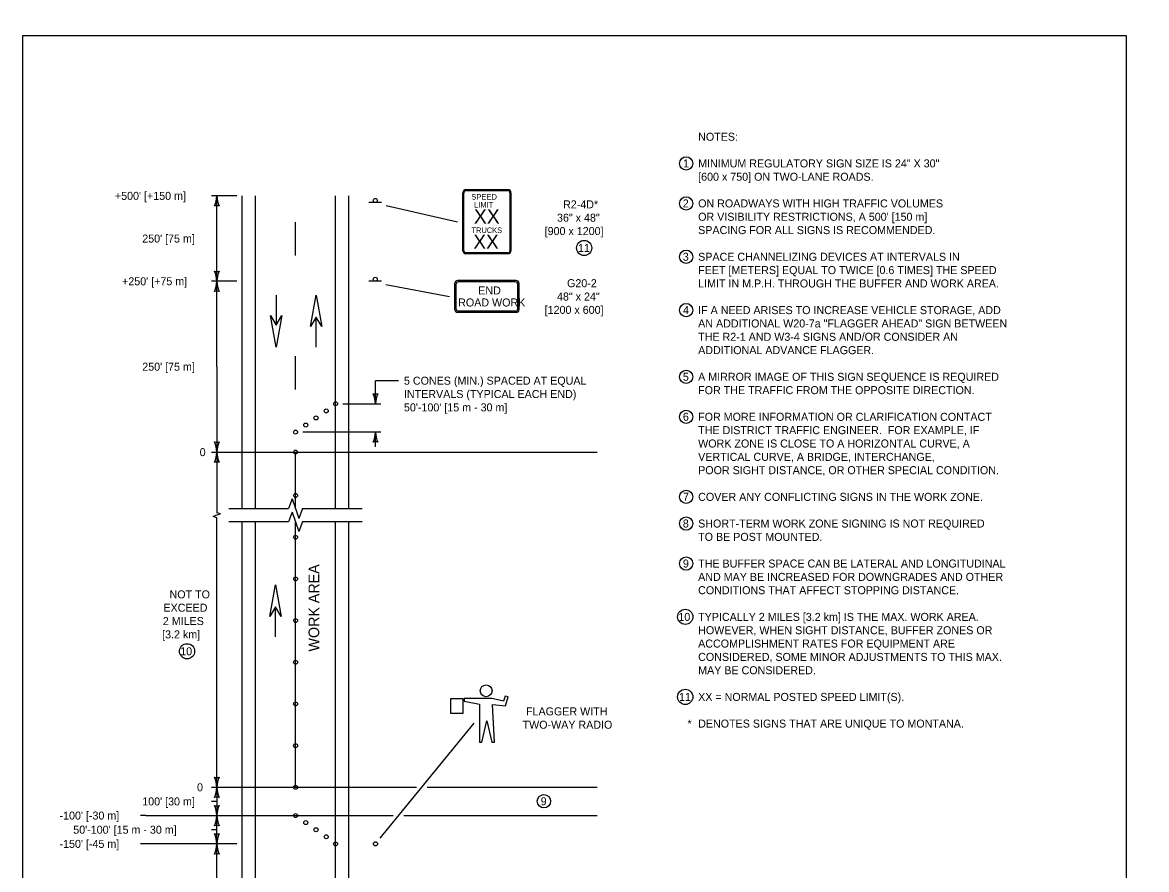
# Model space of a CAD drawing. Extents: x 49987.3 to 50021, y 49987.6 to 50011.4.
# Drawn here: x 50000.34 to 50008.76, y 50005.01 to 50011.36 of the extents above; entities that cross this region are included whole.
import ezdxf

# ---------------------------------------------------------------- set-up
doc = ezdxf.new("R2010")
doc.units = 0
for name, color, linetype in [('Default', 7, 'Continuous'), ('Level 1', 7, 'Continuous'), ('Level 2', 7, 'Continuous'), ('Level 3', 7, 'Continuous'), ('Level 6', 7, 'Continuous')]:
    doc.layers.add(name, color=color, linetype=linetype)

msp = doc.modelspace()

# ---------------------------------------------------------------- linework, layer by layer
at = {"layer": 'Default'}
for p, q in [((50001.7932, 50005.5227), (50001.7532, 50005.5226)), ((50001.2613, 50005.4166), (50001.2213, 50005.4166)), ((50001.7932, 50005.3106), (50001.7532, 50005.3106)), ((50001.2613, 50005.2045), (50001.2213, 50005.2045))]:
    msp.add_line(p, q, dxfattribs=at)
at = {"layer": 'Level 1'}
for p, q in [((50008.7646, 50011.3628), (50008.7646, 50011.3628)), ((50003.9761, 50010.1089), (50003.6611, 50010.1089)), ((50003.9761, 50010.1013), (50003.6611, 50010.1013)), ((50001.9831, 50007.7182), (50001.9831, 50010.0631)), ((50002.0831, 50007.7182), (50002.0831, 50010.0631)), ((50002.6831, 50007.7182), (50002.6831, 50010.0631)), ((50002.783, 50007.7182), (50002.783, 50010.0631)), ((50003.6386, 50009.6515), (50003.6386, 50010.0864)), ((50003.6462, 50009.6515), (50003.6462, 50010.0864)), ((50003.991, 50010.0864), (50003.991, 50009.6515)), ((50003.9986, 50010.0864), (50003.9986, 50009.6515)), ((50003.029, 50010.0128), (50002.9332, 50010.0128)), ((50002.3831, 50009.616), (50002.3831, 50009.8659)), ((50003.8221, 50009.9112), (50003.8221, 50009.9112)), ((50003.9761, 50009.6366), (50003.6611, 50009.6366)), ((50003.9761, 50009.629), (50003.6611, 50009.629)), ((50004.0386, 50009.4281), (50003.5986, 50009.4281)), ((50003.029, 50009.4225), (50002.9332, 50009.4225)), ((50003.5786, 50009.2081), (50003.5786, 50009.4081)), ((50003.5886, 50009.2131), (50003.5886, 50009.4031)), ((50004.0336, 50009.4181), (50003.6036, 50009.4181)), ((50004.0486, 50009.4031), (50004.0486, 50009.2131)), ((50004.0586, 50009.4081), (50004.0586, 50009.2081)), ((50002.2381, 50009.319), (50002.2381, 50009.0929)), ((50002.2384, 50009.319), (50002.2384, 50009.0929)), ((50004.0385, 50009.1881), (50003.5985, 50009.1881)), ((50004.0336, 50009.1981), (50003.6036, 50009.1981)), ((50002.5378, 50008.9287), (50002.5378, 50009.1545)), ((50002.5381, 50008.9287), (50002.5381, 50009.1545)), ((50002.3831, 50008.6118), (50002.3831, 50008.8617)), ((50002.3831, 50007.7167), (50002.3831, 50008.1415)), ((50001.9831, 50001.0011), (50001.9831, 50007.6183)), ((50002.083, 50001.0011), (50002.0831, 50007.6183)), ((50002.3831, 50005.6287), (50002.3831, 50007.6168)), ((50002.683, 50001.0011), (50002.6831, 50007.6183)), ((50002.783, 50001.0011), (50002.783, 50007.6183)), ((50002.2328, 50006.7559), (50002.2328, 50006.982)), ((50002.2331, 50006.7559), (50002.2331, 50006.982)), ((50003.9554, 50006.3127), (50003.9427, 50006.2732)), ((50003.9773, 50006.3072), (50003.9554, 50006.3127)), ((50003.9574, 50006.2383), (50003.9773, 50006.3072)), ((50003.5469, 50006.1813), (50003.5469, 50006.2938)), ((50003.5469, 50006.2938), (50003.6387, 50006.2938)), ((50003.6387, 50006.2938), (50003.6387, 50006.1813)), ((50003.8559, 50006.2932), (50003.6489, 50006.2932)), ((50003.6489, 50006.2932), (50003.6489, 50006.2746)), ((50003.6489, 50006.2746), (50003.7615, 50006.2524)), ((50003.7615, 50006.2524), (50003.7615, 50005.966)), ((50003.9427, 50006.2732), (50003.8559, 50006.2932)), ((50003.8745, 50005.966), (50003.8598, 50006.2494)), ((50003.8598, 50006.2494), (50003.9574, 50006.2383)), ((50003.6387, 50006.1813), (50003.5469, 50006.1813)), ((50003.7796, 50005.966), (50003.8179, 50006.1274)), ((50003.8179, 50006.1274), (50003.8562, 50005.966)), ((50003.7615, 50005.966), (50003.7796, 50005.966)), ((50003.8562, 50005.966), (50003.8745, 50005.966))]:
    msp.add_line(p, q, dxfattribs=at)
for points in [[(50008.6146, 50011.2628), (50000.3356, 50011.2628), (50000.3356, 50000.0624), (50008.6146, 50000.0624)], [(50002.4961, 50009.0823), (50002.5378, 50009.3186), (50002.5797, 50009.0823), (50002.5378, 50009.1545)], [(50002.2802, 50009.1654), (50002.2384, 50008.9287), (50002.1966, 50009.1654), (50002.2384, 50009.0931)], [(50002.1911, 50006.9095), (50002.2328, 50007.1462), (50002.2747, 50006.9095), (50002.2328, 50006.9817)]]:
    msp.add_lwpolyline(points, close=True, dxfattribs=at)
for points in [[(50003.9552, 50006.3126), (50003.9554, 50006.3127)], [(50003.9567, 50006.2386), (50003.9576, 50006.2395)], [(50003.6384, 50006.1813), (50003.6387, 50006.1817)]]:
    msp.add_lwpolyline(points, dxfattribs=at)
for centre, radius in [((50002.981, 50010.0283), 0.0152), ((50002.981, 50009.4379), 0.0152), ((50002.6831, 50008.5037), 0.015), ((50002.6135, 50008.4507), 0.015), ((50002.4599, 50008.3446), 0.015), ((50002.5367, 50008.3977), 0.015), ((50002.3831, 50008.2916), 0.015), ((50002.3831, 50008.1415), 0.015), ((50002.3831, 50007.8163), 0.015), ((50002.3831, 50007.5038), 0.015), ((50002.3831, 50007.1913), 0.015), ((50002.3831, 50006.8788), 0.015), ((50002.3831, 50006.5663), 0.015), ((50003.8123, 50006.352), 0.0442), ((50002.3831, 50006.2538), 0.015), ((50002.3831, 50005.9413), 0.015), ((50002.3831, 50005.6288), 0.015), ((50002.3831, 50005.4166), 0.015), ((50002.4599, 50005.3636), 0.015), ((50002.5367, 50005.3106), 0.015), ((50002.6135, 50005.2575), 0.015), ((50002.6831, 50005.2045), 0.015), ((50002.983, 50005.2045), 0.0152)]:
    msp.add_circle(centre, radius, dxfattribs=at)
for centre, radius, start, end in [((50003.6611, 50010.0864), 0.0225, 90, 180), ((50003.6611, 50010.0864), 0.0149, 90, 180), ((50003.9761, 50010.0864), 0.0225, 0, 90), ((50003.9761, 50010.0864), 0.0149, 0, 90), ((50003.6611, 50009.6515), 0.0225, 180, 270), ((50003.6611, 50009.6515), 0.0149, 180, 270), ((50003.9761, 50009.6515), 0.0225, 270, 0), ((50003.9761, 50009.6515), 0.0149, 270, 0), ((50003.5986, 50009.4081), 0.02, 90, 180), ((50004.0386, 50009.4081), 0.02, 360, 90), ((50003.6036, 50009.4031), 0.015, 90, 180), ((50004.0336, 50009.4031), 0.015, 360, 90), ((50003.5985, 50009.2081), 0.02, 180, 270), ((50003.6036, 50009.2131), 0.015, 180, 270), ((50004.0336, 50009.2131), 0.015, 270, 360), ((50004.0385, 50009.2081), 0.02, 270, 360)]:
    msp.add_arc(centre, radius, start, end, dxfattribs=at)
at = {"layer": 'Level 2'}
for centre, radius in [((50005.3124, 50010.3062), 0.05), ((50005.3124, 50010.0062), 0.05), ((50004.5478, 50009.6721), 0.0569), ((50005.3124, 50009.6062), 0.05), ((50005.3124, 50009.2062), 0.05), ((50005.3124, 50008.7062), 0.05), ((50005.3124, 50008.4062), 0.05), ((50005.3124, 50007.8062), 0.05), ((50005.3124, 50007.6062), 0.05), ((50005.3124, 50007.3062), 0.05), ((50005.3056, 50006.9062), 0.0569), ((50001.5698, 50006.6483), 0.0569), ((50005.3056, 50006.3062), 0.0569), ((50004.2461, 50005.5238), 0.05)]:
    msp.add_circle(centre, radius, dxfattribs=at)
at = {"layer": 'Level 3'}
for p, q in [((50001.9431, 50010.0631), (50001.7531, 50010.0631)), ((50001.7931, 50009.4225), (50001.7931, 50010.0631)), ((50003.0622, 50009.9905), (50003.5986, 50009.8689)), ((50001.9431, 50009.4225), (50001.7531, 50009.4225)), ((50001.9431, 50009.4225), (50001.7532, 50009.4225)), ((50001.7932, 50008.782), (50001.7932, 50009.4225)), ((50003.0602, 50009.3975), (50003.5386, 50009.3081)), ((50001.7932, 50008.782), (50001.7932, 50008.1415)), ((50002.983, 50008.5037), (50002.983, 50008.6771)), ((50003.1563, 50008.6771), (50002.983, 50008.6771)), ((50002.7381, 50008.5037), (50003.023, 50008.5037)), ((50003.023, 50008.2916), (50002.4381, 50008.2916)), ((50002.983, 50008.1815), (50002.983, 50008.2916)), ((50001.7532, 50008.1415), (50004.6462, 50008.1415)), ((50001.7932, 50008.1415), (50001.7932, 50007.6876)), ((50001.7932, 50007.6682), (50001.7658, 50007.6585)), ((50001.7932, 50007.6488), (50001.7658, 50007.6585)), ((50001.8206, 50007.6779), (50001.7932, 50007.6876)), ((50001.8206, 50007.6779), (50001.7932, 50007.6682)), ((50001.7932, 50005.6287), (50001.7932, 50007.6488)), ((50003.0179, 50005.2473), (50003.7215, 50006.1092)), ((50001.7531, 50005.6287), (50003.2893, 50005.6287)), ((50001.7932, 50005.6287), (50001.7932, 50005.4166)), ((50003.3693, 50005.6287), (50004.6461, 50005.6287)), ((50001.2613, 50005.4166), (50003.1162, 50005.4166)), ((50001.7932, 50005.2045), (50001.7932, 50005.4166)), ((50003.1962, 50005.4166), (50004.6461, 50005.4166)), ((50001.9431, 50005.2045), (50001.2613, 50005.2045)), ((50001.7932, 50001.3045), (50001.7932, 50005.2045))]:
    msp.add_line(p, q, dxfattribs=at)
for centre, radius, start, end in [((50001.571, 50010.0722), 0.2223, 337.45601, 357.63952), ((50002.0259, 50010.0745), 0.233, 182.82731, 202.07716), ((50001.7931, 50009.9348), 0.0548, 72.13882, 107.86118), ((50001.7931, 50009.5507), 0.0548, 252.13882, 287.86118), ((50001.5604, 50009.411), 0.233, 2.82731, 22.07716), ((50002.0153, 50009.4134), 0.2223, 157.45601, 177.63952), ((50001.571, 50009.4317), 0.2223, 337.45601, 357.63952), ((50001.7932, 50009.2943), 0.0548, 72.13882, 107.86118), ((50002.0259, 50009.434), 0.233, 182.82731, 202.07716), ((50002.983, 50008.6319), 0.0548, 252.13882, 287.86118), ((50002.7503, 50008.4922), 0.233, 2.82731, 22.07716), ((50003.2051, 50008.4945), 0.2223, 157.45601, 177.63952), ((50002.7609, 50008.3008), 0.2223, 337.45601, 357.63952), ((50003.2157, 50008.3031), 0.233, 182.82731, 202.07716), ((50001.7932, 50008.2697), 0.0548, 252.13882, 287.86118), ((50001.5605, 50008.13), 0.233, 2.82731, 22.07716), ((50002.0153, 50008.1323), 0.2223, 157.45601, 177.63952), ((50002.983, 50008.1634), 0.0548, 72.13882, 107.86118), ((50001.5711, 50008.1506), 0.2223, 337.45601, 357.63952), ((50002.0259, 50008.153), 0.233, 182.82731, 202.07716), ((50001.7932, 50008.0133), 0.0548, 72.13882, 107.86118), ((50001.7932, 50005.7569), 0.0548, 252.13882, 287.86118), ((50001.5605, 50005.6172), 0.233, 2.82731, 22.07716), ((50002.0153, 50005.6196), 0.2223, 157.45601, 177.63952), ((50001.5711, 50005.6379), 0.2223, 337.45601, 357.63952), ((50001.7932, 50005.5005), 0.0548, 72.13882, 107.86118), ((50002.0259, 50005.6402), 0.233, 182.82731, 202.07716), ((50001.7932, 50005.5448), 0.0548, 252.13882, 287.86118), ((50001.5605, 50005.4051), 0.233, 2.82731, 22.07716), ((50002.0153, 50005.4075), 0.2223, 157.45601, 177.63952), ((50001.571, 50005.4258), 0.2223, 337.45812, 357.64163), ((50002.0259, 50005.4281), 0.233, 182.82942, 202.07927), ((50001.7932, 50005.2884), 0.0548, 72.14093, 107.86329), ((50001.7931, 50005.3327), 0.0548, 252.16466, 287.88702), ((50001.5605, 50005.1929), 0.233, 2.85315, 22.103), ((50002.0153, 50005.1955), 0.2223, 157.48185, 177.66536), ((50001.571, 50005.2137), 0.2223, 337.45812, 357.64163), ((50001.7932, 50005.0763), 0.0548, 72.14093, 107.86329), ((50002.0259, 50005.216), 0.233, 182.82942, 202.07927)]:
    msp.add_arc(centre, radius, start, end, dxfattribs=at)
at = {"layer": 'Level 6'}
for p, q in [((50002.3568, 50007.7914), (50002.3308, 50007.7182)), ((50002.3568, 50007.7914), (50002.3826, 50007.7182)), ((50001.8831, 50007.7182), (50002.3308, 50007.7182)), ((50002.3568, 50007.6913), (50002.3308, 50007.6183)), ((50002.3568, 50007.6913), (50002.3826, 50007.6183)), ((50002.3826, 50007.7182), (50002.4085, 50007.6451)), ((50002.4343, 50007.7182), (50002.4085, 50007.6451)), ((50002.4343, 50007.7182), (50002.883, 50007.7182)), ((50002.3308, 50007.6183), (50001.8831, 50007.6183)), ((50002.3826, 50007.6183), (50002.4085, 50007.5452)), ((50002.4343, 50007.6183), (50002.4085, 50007.5452)), ((50002.883, 50007.6183), (50002.4343, 50007.6183))]:
    msp.add_line(p, q, dxfattribs=at)

# ---------------------------------------------------------------- texts
at = {"layer": 'Level 1'}
for s, height, p in [('SPEED', 0.04121, (50003.7009, 50010.0348)), ('LIMIT', 0.04162, (50003.7227, 50009.9753)), ('XX', 0.10831, (50003.7209, 50009.8543)), ('TRUCKS', 0.04183, (50003.7025, 50009.7841)), ('XX', 0.10679, (50003.7165, 50009.666))]:
    msp.add_text(s, height=height, dxfattribs=at).set_placement(p)
for s, p in [('END', (50003.7534, 50009.3235)), ('ROAD WORK', (50003.6027, 50009.2335))]:
    msp.add_text(s, height=0.06, rotation=360, dxfattribs=at).set_placement(p)
at = {"layer": 'Level 2'}
for s, height, p in [('NOTES:', 0.06, (50005.4024, 50010.4762)), ('1', 0.06, (50005.2897, 50010.2762)), ('MINIMUM REGULATORY SIGN SIZE IS 24" X 30" ', 0.06, (50005.4024, 50010.2762)), ('[600 x 750] ON TWO-LANE ROADS.', 0.06, (50005.4024, 50010.1762)), ("+500' [+150 m]", 0.059993, (50001.0286, 50010.0331)), ('R2-4D*', 0.06, (50004.3895, 50009.9689)), ('2', 0.06, (50005.2874, 50009.9764)), ('ON ROADWAYS WITH HIGH TRAFFIC VOLUMES', 0.06, (50005.4024, 50009.9762)), ("OR VISIBILITY RESTRICTIONS, A 500' [150 m] ", 0.06, (50005.4024, 50009.8762)), ('36" x 48"', 0.06, (50004.344, 50009.8689)), ("250' [75 m]", 0.059993, (50001.2337, 50009.7128)), ('[900 x 1200]', 0.06, (50004.2515, 50009.7689)), ('SPACING FOR ALL SIGNS IS RECOMMENDED.', 0.06, (50005.4024, 50009.7762)), ('11', 0.06, (50004.5011, 50009.6421)), ('3', 0.06, (50005.2873, 50009.5764)), ('SPACE CHANNELIZING DEVICES AT INTERVALS IN ', 0.06, (50005.4024, 50009.5762)), ('FEET [METERS] EQUAL TO TWICE [0.6 TIMES] THE SPEED ', 0.06, (50005.4024, 50009.4762)), ("+250' [+75 m]", 0.059993, (50001.0825, 50009.3925)), ('G20-2', 0.05999, (50004.4192, 50009.3781)), ('LIMIT IN M.P.H. THROUGH THE BUFFER AND WORK AREA.', 0.06, (50005.4024, 50009.3762)), ('48" x 24"', 0.05999, (50004.344, 50009.2781)), ('[1200 x 600]', 0.059993, (50004.2515, 50009.1781)), ('4', 0.06, (50005.2886, 50009.1764)), ('IF A NEED ARISES TO INCREASE VEHICLE STORAGE, ADD', 0.06, (50005.4024, 50009.1762)), ('AN ADDITIONAL W20-7a "FLAGGER AHEAD" SIGN BETWEEN ', 0.06, (50005.4024, 50009.0762)), ('THE R2-1 AND W3-4 SIGNS AND/OR CONSIDER AN ', 0.06, (50005.4024, 50008.9762)), ('ADDITIONAL ADVANCE FLAGGER.', 0.06, (50005.4024, 50008.8762)), ("250' [75 m]", 0.059993, (50001.2337, 50008.752)), ('5 CONES (MIN.) SPACED AT EQUAL ', 0.059993, (50003.1963, 50008.6471)), ('5', 0.06, (50005.2877, 50008.6764)), ('A MIRROR IMAGE OF THIS SIGN SEQUENCE IS REQUIRED ', 0.06, (50005.4024, 50008.6762)), ('INTERVALS (TYPICAL EACH END)', 0.059993, (50003.1963, 50008.5471)), ('FOR THE TRAFFIC FROM THE OPPOSITE DIRECTION.', 0.06, (50005.4024, 50008.5762)), ("50'-100' [15 m - 30 m]", 0.059993, (50003.1963, 50008.4471)), ('6', 0.06, (50005.288, 50008.3764)), ('FOR MORE INFORMATION OR CLARIFICATION CONTACT ', 0.06, (50005.4024, 50008.3762)), ('THE DISTRICT TRAFFIC ENGINEER.  FOR EXAMPLE, IF ', 0.06, (50005.4024, 50008.2762)), ('0', 0.06, (50001.6644, 50008.1115)), ('WORK ZONE IS CLOSE TO A HORIZONTAL CURVE, A ', 0.06, (50005.4024, 50008.1762)), ('VERTICAL CURVE, A BRIDGE, INTERCHANGE, ', 0.06, (50005.4024, 50008.0762)), ('POOR SIGHT DISTANCE, OR OTHER SPECIAL CONDITION.', 0.06, (50005.4024, 50007.9762)), ('7', 0.06, (50005.2887, 50007.7764)), ('COVER ANY CONFLICTING SIGNS IN THE WORK ZONE.', 0.06, (50005.4024, 50007.7762)), ('8', 0.06, (50005.2875, 50007.5764)), ('SHORT-TERM WORK ZONE SIGNING IS NOT REQUIRED ', 0.06, (50005.4024, 50007.5762)), ('TO BE POST MOUNTED.', 0.06, (50005.4024, 50007.4762)), ('9', 0.06, (50005.288, 50007.2764)), ('THE BUFFER SPACE CAN BE LATERAL AND LONGITUDINAL', 0.06, (50005.4024, 50007.2762)), ('AND MAY BE INCREASED FOR DOWNGRADES AND OTHER', 0.06, (50005.4024, 50007.1762)), ('NOT TO', 0.06, (50001.4383, 50007.0451)), ('CONDITIONS THAT AFFECT STOPPING DISTANCE.', 0.06, (50005.4024, 50007.0762)), ('EXCEED', 0.06, (50001.3926, 50006.9451)), ('2 MILES', 0.06, (50001.388, 50006.8451)), ('10', 0.06, (50005.254, 50006.8762)), ('TYPICALLY 2 MILES [3.2 km] IS THE MAX. WORK AREA.  ', 0.06, (50005.4024, 50006.8762)), ('HOWEVER, WHEN SIGHT DISTANCE, BUFFER ZONES OR ', 0.06, (50005.4024, 50006.7762)), ('[3.2 km]', 0.06, (50001.3827, 50006.7451)), ('ACCOMPLISHMENT RATES FOR EQUIPMENT ARE ', 0.06, (50005.4024, 50006.6762)), ('10', 0.06, (50001.5184, 50006.6183)), ('CONSIDERED, SOME MINOR ADJUSTMENTS TO THIS MAX.', 0.06, (50005.4024, 50006.5762)), ('MAY BE CONSIDERED.', 0.06, (50005.4024, 50006.4762)), ('11', 0.06, (50005.2589, 50006.2762)), ('XX = NORMAL POSTED SPEED LIMIT(S).', 0.06, (50005.4024, 50006.2762)), ('FLAGGER WITH', 0.06, (50004.1115, 50006.1677)), ('TWO-WAY RADIO', 0.06, (50004.0858, 50006.0677)), ('*', 0.06, (50005.3226, 50006.0762)), ('DENOTES SIGNS THAT ARE UNIQUE TO MONTANA.', 0.06, (50005.4024, 50006.0762)), (' 0', 0.05999, (50001.6223, 50005.5987)), ("100' [30 m]", 0.059993, (50001.2337, 50005.4927)), ('9', 0.06, (50004.2216, 50005.4938)), ("-100' [-30 m]", 0.059993, (50000.6133, 50005.3866)), ("50'-100' [15 m - 30 m]", 0.059993, (50000.7164, 50005.2806)), ("-150' [-45 m]", 0.059993, (50000.6133, 50005.1745))]:
    msp.add_text(s, height=height, dxfattribs=at).set_placement(p)
msp.add_text('WORK AREA', height=0.08, rotation=90, dxfattribs=at).set_placement((50002.5607, 50006.6466))

doc.saveas('drawing.dxf')
